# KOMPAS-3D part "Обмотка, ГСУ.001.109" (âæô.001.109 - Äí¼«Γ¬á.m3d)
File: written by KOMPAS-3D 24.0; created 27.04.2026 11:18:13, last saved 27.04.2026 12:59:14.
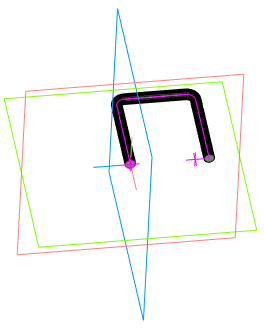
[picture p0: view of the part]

Document properties: Автор: User7; Полное имя файла: C:\Users\User7\Desktop\олимп\ГСУ.001.109 - Обмотка.m3d

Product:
- Part/product: Обмотка  | designation ГСУ.001.109
    Масса: 0.002122

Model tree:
1. Эскиз:1
2. Эскиз:2
3. Элемент по траектории:1
     Длина траектории = 59.9232

Expressions: 23-2.43/2
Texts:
  ГСУ.001.109
  Шаг 2
  Шаг 1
